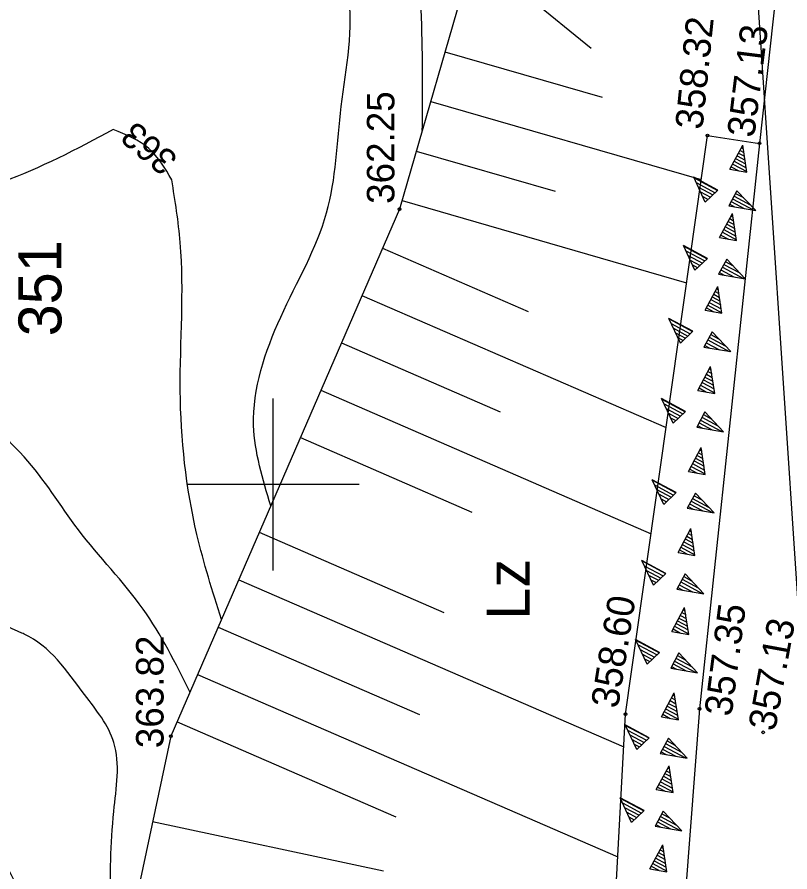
# Model space of a CAD drawing. Extents: x 4635329 to 4651863, y 5356628 to 5367582.
# Drawn here: x 4651179.57 to 4651202.03, y 5356645.09 to 5356669.94 of the extents above; entities that cross this region are included whole.
import ezdxf

# ---------------------------------------------------------------- set-up
doc = ezdxf.new("R2010")
doc.units = 0
for name, color, linetype in [('Level 12', 7, 'Continuous'), ('Level 4', 7, 'Continuous'), ('Level 44', 7, 'Continuous'), ('Level 45', 7, 'Continuous'), ('Level 46', 7, 'Continuous'), ('Level 47', 7, 'Continuous'), ('Level 48', 7, 'Continuous'), ('Level 49', 7, 'Continuous'), ('Level 5', 7, 'Continuous'), ('Level 50', 7, 'Continuous'), ('Level 60', 7, 'Continuous')]:
    doc.layers.add(name, color=color, linetype=linetype)

msp = doc.modelspace()

# ---------------------------------------------------------------- linework, layer by layer
at = {"layer": 'Level 4'}
msp.add_line((4651203.591, 5356632.939), (4651200.98, 5356672.325), dxfattribs=at)
at = {"layer": 'Level 44'}
for centre in [(4651199.635, 5356666.497), (4651201.145, 5356666.267), (4651190.685, 5356664.357), (4651197.255, 5356649.677), (4651199.405, 5356649.827), (4651201.255, 5356649.147), (4651184.035, 5356649.037)]:
    msp.add_circle(centre, 0.04, dxfattribs=at)
at = {"layer": 'Level 46'}
msp.add_line((4651179.706, 5356652.031), (4651177.706, 5356652.91), dxfattribs=at)
for points in [[(4651186.942, 5356655.734), (4651186.443, 5356658.066), (4651187.231, 5356661.219), (4651188.565, 5356664.25), (4651188.99, 5356667.342), (4651189.172, 5356670.677), (4651183.41, 5356675.407), (4651180.62, 5356675.589), (4651178.861, 5356675.735)], [(4651191.346, 5356666.645), (4651191.346, 5356669.024), (4651191.164, 5356672.662), (4651191.037, 5356674.114)], [(4651182.363, 5356666.668), (4651175.94, 5356664.78), (4651173.696, 5356665.325), (4651173.402, 5356665.355)], [(4651184.062, 5356665.204), (4651183.4, 5356666.114), (4651182.363, 5356666.668)], [(4651185.507, 5356652.429), (4651184.795, 5356654.897), (4651184.31, 5356659.08), (4651184.31, 5356663.385), (4651184.062, 5356665.204)], [(4651184.591, 5356650.319), (4651183.228, 5356652.73), (4651181.348, 5356655.034), (4651179.771, 5356657.156), (4651174.07, 5356659.581), (4651171.401, 5356659.824), (4651170.74, 5356660.291)], [(4651182.533, 5356641.982), (4651182.318, 5356644.059), (4651182.379, 5356646.848), (4651182.379, 5356648.849), (4651181.53, 5356650.244), (4651179.771, 5356652.002), (4651179.706, 5356652.031)], [(4651181.627, 5356637.725), (4651181.408, 5356639.209), (4651180.499, 5356642.422), (4651178.74, 5356646.121), (4651173.827, 5356650.062), (4651172.468, 5356650.413)]]:
    msp.add_spline(points, degree=3, dxfattribs=at)
at = {"layer": 'Level 48'}
for p, q in [((4651192.905, 5356671.773), (4651196.255, 5356669.031)), ((4651192.005, 5356668.926), (4651196.576, 5356667.606)), ((4651191.589, 5356667.485), (4651199.453, 5356665.213)), ((4651191.172, 5356666.044), (4651195.207, 5356664.879)), ((4651190.756, 5356664.603), (4651199.029, 5356662.213)), ((4651190.19, 5356663.216), (4651194.42, 5356661.38)), ((4651189.592, 5356661.84), (4651198.433, 5356658.003)), ((4651188.995, 5356660.464), (4651193.605, 5356658.463)), ((4651188.398, 5356659.088), (4651197.997, 5356654.921)), ((4651187.801, 5356657.712), (4651192.79, 5356655.547)), ((4651186.606, 5356654.96), (4651191.974, 5356652.63)), ((4651186.009, 5356653.584), (4651197.203, 5356648.725)), ((4651185.412, 5356652.208), (4651191.264, 5356649.668)), ((4651184.814, 5356650.832), (4651197.029, 5356645.53)), ((4651184.217, 5356649.456), (4651190.579, 5356646.695)), ((4651183.506, 5356646.55), (4651190.217, 5356645.121))]:
    msp.add_line(p, q, dxfattribs=at)
for points in [[(4651197.655, 5356677.577), (4651192.785, 5356671.627), (4651190.685, 5356664.357), (4651184.035, 5356649.037), (4651181.425, 5356636.777)], [(4651196.425, 5356634.457), (4651197.255, 5356649.677), (4651199.635, 5356666.497), (4651201.145, 5356666.267)]]:
    msp.add_lwpolyline(points, dxfattribs=at)
at = {"layer": 'Level 49'}
for p, q in [((4651200.289, 5356665.514), (4651200.663, 5356666.21)), ((4651200.583, 5356666.062), (4651200.694, 5356666.003)), ((4651200.626, 5356666.142), (4651200.677, 5356666.114)), ((4651200.782, 5356665.428), (4651200.663, 5356666.21)), ((4651200.455, 5356665.824), (4651200.744, 5356665.669)), ((4651200.498, 5356665.904), (4651200.728, 5356665.78)), ((4651200.541, 5356665.983), (4651200.712, 5356665.891)), ((4651200.328, 5356665.587), (4651200.547, 5356665.469)), ((4651200.37, 5356665.666), (4651200.779, 5356665.446)), ((4651200.413, 5356665.745), (4651200.762, 5356665.558)), ((4651200.289, 5356665.514), (4651200.782, 5356665.428)), ((4651199.935, 5356664.905), (4651199.239, 5356665.279)), ((4651199.571, 5356664.561), (4651199.239, 5356665.279)), ((4651199.245, 5356665.264), (4651199.928, 5356664.898)), ((4651199.308, 5356665.128), (4651199.859, 5356664.833)), ((4651199.372, 5356664.992), (4651199.79, 5356664.767)), ((4651199.435, 5356664.856), (4651199.721, 5356664.702)), ((4651199.935, 5356664.905), (4651199.571, 5356664.561)), ((4651200.494, 5356664.889), (4651200.258, 5356664.448)), ((4651200.454, 5356664.813), (4651200.681, 5356664.691)), ((4651201.037, 5356664.314), (4651200.494, 5356664.889)), ((4651199.498, 5356664.72), (4651199.652, 5356664.637)), ((4651199.561, 5356664.584), (4651199.583, 5356664.572)), ((4651200.326, 5356664.575), (4651200.706, 5356664.371)), ((4651200.368, 5356664.654), (4651200.987, 5356664.322)), ((4651200.411, 5356664.734), (4651200.876, 5356664.484)), ((4651200.258, 5356664.448), (4651201.037, 5356664.314)), ((4651200.283, 5356664.496), (4651200.426, 5356664.419)), ((4651199.988, 5356663.53), (4651200.362, 5356664.226)), ((4651200.283, 5356664.078), (4651200.394, 5356664.018)), ((4651200.325, 5356664.157), (4651200.376, 5356664.13)), ((4651200.481, 5356663.443), (4651200.362, 5356664.226)), ((4651200.155, 5356663.84), (4651200.444, 5356663.685)), ((4651200.197, 5356663.919), (4651200.427, 5356663.796)), ((4651200.24, 5356663.999), (4651200.411, 5356663.907)), ((4651200.027, 5356663.602), (4651200.246, 5356663.484)), ((4651200.07, 5356663.681), (4651200.478, 5356663.462)), ((4651200.112, 5356663.761), (4651200.461, 5356663.573)), ((4651199.988, 5356663.53), (4651200.481, 5356663.443)), ((4651199.635, 5356662.921), (4651198.938, 5356663.295)), ((4651199.271, 5356662.577), (4651198.938, 5356663.295)), ((4651198.945, 5356663.28), (4651199.628, 5356662.913)), ((4651199.008, 5356663.144), (4651199.559, 5356662.848)), ((4651199.071, 5356663.008), (4651199.49, 5356662.783)), ((4651199.134, 5356662.872), (4651199.42, 5356662.718)), ((4651199.635, 5356662.921), (4651199.271, 5356662.577)), ((4651200.194, 5356662.904), (4651199.957, 5356662.464)), ((4651200.153, 5356662.828), (4651200.38, 5356662.706)), ((4651200.736, 5356662.329), (4651200.194, 5356662.904)), ((4651199.197, 5356662.736), (4651199.351, 5356662.653)), ((4651199.26, 5356662.6), (4651199.282, 5356662.588)), ((4651200.025, 5356662.591), (4651200.406, 5356662.386)), ((4651200.068, 5356662.67), (4651200.686, 5356662.338)), ((4651200.11, 5356662.749), (4651200.576, 5356662.499)), ((4651199.957, 5356662.464), (4651200.736, 5356662.329)), ((4651199.983, 5356662.511), (4651200.125, 5356662.435)), ((4651199.565, 5356661.413), (4651199.939, 5356662.109)), ((4651200.057, 5356661.326), (4651199.939, 5356662.109)), ((4651199.816, 5356661.881), (4651199.987, 5356661.79)), ((4651199.859, 5356661.961), (4651199.97, 5356661.901)), ((4651199.902, 5356662.04), (4651199.953, 5356662.013)), ((4651199.689, 5356661.644), (4651200.038, 5356661.456)), ((4651199.731, 5356661.723), (4651200.02, 5356661.568)), ((4651199.774, 5356661.802), (4651200.004, 5356661.679)), ((4651199.565, 5356661.413), (4651200.057, 5356661.326)), ((4651199.604, 5356661.485), (4651199.823, 5356661.367)), ((4651199.646, 5356661.564), (4651200.055, 5356661.345)), ((4651199.211, 5356660.803), (4651198.515, 5356661.178)), ((4651198.847, 5356660.46), (4651198.515, 5356661.178)), ((4651198.521, 5356661.163), (4651199.204, 5356660.796)), ((4651198.584, 5356661.027), (4651199.135, 5356660.731)), ((4651198.647, 5356660.891), (4651199.066, 5356660.666)), ((4651198.711, 5356660.755), (4651198.997, 5356660.601)), ((4651198.774, 5356660.619), (4651198.928, 5356660.536)), ((4651199.211, 5356660.803), (4651198.847, 5356660.46)), ((4651199.77, 5356660.787), (4651199.534, 5356660.347)), ((4651199.687, 5356660.632), (4651200.152, 5356660.382)), ((4651199.729, 5356660.711), (4651199.957, 5356660.589)), ((4651200.313, 5356660.212), (4651199.77, 5356660.787)), ((4651198.837, 5356660.482), (4651198.859, 5356660.471)), ((4651199.534, 5356660.347), (4651200.313, 5356660.212)), ((4651199.559, 5356660.394), (4651199.702, 5356660.318)), ((4651199.602, 5356660.473), (4651199.982, 5356660.269)), ((4651199.644, 5356660.553), (4651200.263, 5356660.221)), ((4651199.353, 5356659.084), (4651199.727, 5356659.78)), ((4651199.647, 5356659.632), (4651199.758, 5356659.572)), ((4651199.69, 5356659.711), (4651199.741, 5356659.684)), ((4651199.846, 5356658.997), (4651199.727, 5356659.78)), ((4651199.52, 5356659.394), (4651199.808, 5356659.239)), ((4651199.562, 5356659.473), (4651199.792, 5356659.35)), ((4651199.605, 5356659.553), (4651199.776, 5356659.461)), ((4651199.392, 5356659.156), (4651199.611, 5356659.038)), ((4651199.434, 5356659.235), (4651199.843, 5356659.016)), ((4651199.477, 5356659.315), (4651199.826, 5356659.127)), ((4651199, 5356658.475), (4651198.303, 5356658.849)), ((4651198.636, 5356658.131), (4651198.303, 5356658.849)), ((4651199.353, 5356659.084), (4651199.846, 5356658.997)), ((4651198.309, 5356658.834), (4651198.992, 5356658.467)), ((4651198.373, 5356658.698), (4651198.923, 5356658.402)), ((4651198.436, 5356658.562), (4651198.854, 5356658.337)), ((4651198.499, 5356658.426), (4651198.785, 5356658.272)), ((4651199, 5356658.475), (4651198.636, 5356658.131)), ((4651199.558, 5356658.458), (4651199.322, 5356658.018)), ((4651199.518, 5356658.382), (4651199.745, 5356658.26)), ((4651200.101, 5356657.883), (4651199.558, 5356658.458)), ((4651198.562, 5356658.29), (4651198.716, 5356658.207)), ((4651198.625, 5356658.154), (4651198.647, 5356658.142)), ((4651199.39, 5356658.145), (4651199.77, 5356657.94)), ((4651199.432, 5356658.224), (4651200.051, 5356657.892)), ((4651199.475, 5356658.303), (4651199.94, 5356658.053)), ((4651199.322, 5356658.018), (4651200.101, 5356657.883)), ((4651199.347, 5356658.065), (4651199.49, 5356657.989)), ((4651199.081, 5356656.725), (4651199.455, 5356657.421)), ((4651199.573, 5356656.638), (4651199.455, 5356657.421)), ((4651199.29, 5356657.114), (4651199.52, 5356656.991)), ((4651199.332, 5356657.193), (4651199.503, 5356657.102)), ((4651199.375, 5356657.273), (4651199.486, 5356657.213)), ((4651199.418, 5356657.352), (4651199.469, 5356657.325)), ((4651199.162, 5356656.876), (4651199.571, 5356656.657)), ((4651199.205, 5356656.956), (4651199.554, 5356656.768)), ((4651199.247, 5356657.035), (4651199.536, 5356656.88)), ((4651199.081, 5356656.725), (4651199.573, 5356656.638)), ((4651199.119, 5356656.797), (4651199.339, 5356656.679)), ((4651198.727, 5356656.115), (4651198.03, 5356656.49)), ((4651198.363, 5356655.772), (4651198.03, 5356656.49)), ((4651198.037, 5356656.475), (4651198.72, 5356656.108)), ((4651198.1, 5356656.339), (4651198.651, 5356656.043)), ((4651198.163, 5356656.203), (4651198.582, 5356655.978)), ((4651198.727, 5356656.115), (4651198.363, 5356655.772)), ((4651198.227, 5356656.067), (4651198.513, 5356655.913)), ((4651198.29, 5356655.93), (4651198.444, 5356655.848)), ((4651199.286, 5356656.099), (4651199.049, 5356655.659)), ((4651199.16, 5356655.865), (4651199.779, 5356655.533)), ((4651199.203, 5356655.944), (4651199.668, 5356655.694)), ((4651199.245, 5356656.023), (4651199.473, 5356655.901)), ((4651199.828, 5356655.524), (4651199.286, 5356656.099)), ((4651198.353, 5356655.794), (4651198.375, 5356655.783)), ((4651199.049, 5356655.659), (4651199.828, 5356655.524)), ((4651199.075, 5356655.706), (4651199.218, 5356655.629)), ((4651199.118, 5356655.785), (4651199.498, 5356655.581)), ((4651198.78, 5356654.377), (4651199.154, 5356655.073)), ((4651199.074, 5356654.925), (4651199.185, 5356654.866)), ((4651199.117, 5356655.005), (4651199.168, 5356654.977)), ((4651199.273, 5356654.291), (4651199.154, 5356655.073)), ((4651198.946, 5356654.687), (4651199.235, 5356654.532)), ((4651198.989, 5356654.767), (4651199.219, 5356654.643)), ((4651199.032, 5356654.846), (4651199.203, 5356654.754)), ((4651198.78, 5356654.377), (4651199.273, 5356654.291)), ((4651198.819, 5356654.45), (4651199.038, 5356654.332)), ((4651198.861, 5356654.529), (4651199.27, 5356654.309)), ((4651198.904, 5356654.608), (4651199.253, 5356654.421)), ((4651198.426, 5356653.768), (4651197.73, 5356654.142)), ((4651198.063, 5356653.424), (4651197.73, 5356654.142)), ((4651197.736, 5356654.127), (4651198.419, 5356653.761)), ((4651197.799, 5356653.991), (4651198.35, 5356653.696)), ((4651197.863, 5356653.855), (4651198.281, 5356653.63)), ((4651197.926, 5356653.719), (4651198.212, 5356653.565)), ((4651198.426, 5356653.768), (4651198.063, 5356653.424)), ((4651198.985, 5356653.752), (4651198.749, 5356653.311)), ((4651198.945, 5356653.676), (4651199.172, 5356653.554)), ((4651199.528, 5356653.177), (4651198.985, 5356653.752)), ((4651197.989, 5356653.583), (4651198.143, 5356653.5)), ((4651198.052, 5356653.447), (4651198.074, 5356653.435)), ((4651198.817, 5356653.438), (4651199.197, 5356653.234)), ((4651198.859, 5356653.517), (4651199.478, 5356653.185)), ((4651198.902, 5356653.597), (4651199.367, 5356653.347)), ((4651198.749, 5356653.311), (4651199.528, 5356653.177)), ((4651198.774, 5356653.359), (4651198.917, 5356653.282)), ((4651198.598, 5356652.079), (4651198.972, 5356652.775)), ((4651198.935, 5356652.706), (4651198.986, 5356652.679)), ((4651199.091, 5356651.992), (4651198.972, 5356652.775)), ((4651198.765, 5356652.389), (4651199.054, 5356652.234)), ((4651198.807, 5356652.468), (4651199.037, 5356652.345)), ((4651198.85, 5356652.547), (4651199.021, 5356652.456)), ((4651198.893, 5356652.627), (4651199.004, 5356652.567)), ((4651198.637, 5356652.151), (4651198.856, 5356652.033)), ((4651198.68, 5356652.23), (4651199.088, 5356652.011)), ((4651198.722, 5356652.31), (4651199.071, 5356652.122)), ((4651198.598, 5356652.079), (4651199.091, 5356651.992)), ((4651198.245, 5356651.469), (4651197.548, 5356651.844)), ((4651197.881, 5356651.126), (4651197.548, 5356651.844)), ((4651197.555, 5356651.829), (4651198.238, 5356651.462)), ((4651197.618, 5356651.693), (4651198.169, 5356651.397)), ((4651197.681, 5356651.557), (4651198.1, 5356651.332)), ((4651197.744, 5356651.421), (4651198.031, 5356651.267)), ((4651198.245, 5356651.469), (4651197.881, 5356651.126)), ((4651198.804, 5356651.453), (4651198.567, 5356651.013)), ((4651199.346, 5356650.878), (4651198.804, 5356651.453)), ((4651197.807, 5356651.284), (4651197.961, 5356651.202)), ((4651197.87, 5356651.148), (4651197.892, 5356651.137)), ((4651198.678, 5356651.219), (4651199.296, 5356650.887)), ((4651198.72, 5356651.298), (4651199.186, 5356651.048)), ((4651198.763, 5356651.377), (4651198.99, 5356651.255)), ((4651198.567, 5356651.013), (4651199.346, 5356650.878)), ((4651198.593, 5356651.06), (4651198.735, 5356650.983)), ((4651198.635, 5356651.139), (4651199.016, 5356650.935)), ((4651198.296, 5356649.599), (4651198.67, 5356650.295)), ((4651198.633, 5356650.226), (4651198.684, 5356650.198)), ((4651198.789, 5356649.512), (4651198.67, 5356650.295)), ((4651198.462, 5356649.909), (4651198.751, 5356649.754)), ((4651198.505, 5356649.988), (4651198.735, 5356649.864)), ((4651198.548, 5356650.067), (4651198.718, 5356649.975)), ((4651198.59, 5356650.147), (4651198.701, 5356650.087)), ((4651198.335, 5356649.671), (4651198.554, 5356649.553)), ((4651198.377, 5356649.75), (4651198.786, 5356649.531)), ((4651198.42, 5356649.829), (4651198.769, 5356649.642)), ((4651198.296, 5356649.599), (4651198.789, 5356649.512)), ((4651197.942, 5356648.989), (4651197.246, 5356649.364)), ((4651197.578, 5356648.646), (4651197.246, 5356649.364)), ((4651197.252, 5356649.349), (4651197.935, 5356648.982)), ((4651197.315, 5356649.213), (4651197.866, 5356648.917)), ((4651197.379, 5356649.077), (4651197.797, 5356648.852)), ((4651197.442, 5356648.94), (4651197.728, 5356648.787)), ((4651197.942, 5356648.989), (4651197.578, 5356648.646)), ((4651198.501, 5356648.973), (4651198.265, 5356648.532)), ((4651199.044, 5356648.398), (4651198.501, 5356648.973)), ((4651197.505, 5356648.804), (4651197.659, 5356648.722)), ((4651197.568, 5356648.668), (4651197.59, 5356648.656)), ((4651198.333, 5356648.659), (4651198.713, 5356648.455)), ((4651198.375, 5356648.739), (4651198.994, 5356648.406)), ((4651198.418, 5356648.818), (4651198.883, 5356648.568)), ((4651198.46, 5356648.897), (4651198.688, 5356648.775)), ((4651198.265, 5356648.532), (4651199.044, 5356648.398)), ((4651198.29, 5356648.58), (4651198.433, 5356648.503)), ((4651198.145, 5356647.481), (4651198.518, 5356648.177)), ((4651198.637, 5356647.395), (4651198.518, 5356648.177)), ((4651198.396, 5356647.95), (4651198.567, 5356647.858)), ((4651198.439, 5356648.029), (4651198.55, 5356647.97)), ((4651198.481, 5356648.109), (4651198.533, 5356648.081)), ((4651198.268, 5356647.712), (4651198.617, 5356647.525)), ((4651198.311, 5356647.792), (4651198.6, 5356647.636)), ((4651198.354, 5356647.871), (4651198.584, 5356647.747)), ((4651198.145, 5356647.481), (4651198.637, 5356647.395)), ((4651198.183, 5356647.554), (4651198.403, 5356647.436)), ((4651198.226, 5356647.633), (4651198.635, 5356647.413)), ((4651197.791, 5356646.872), (4651197.094, 5356647.246)), ((4651197.427, 5356646.528), (4651197.094, 5356647.246)), ((4651197.101, 5356647.232), (4651197.784, 5356646.865)), ((4651197.164, 5356647.095), (4651197.715, 5356646.8)), ((4651197.227, 5356646.959), (4651197.646, 5356646.735)), ((4651197.29, 5356646.823), (4651197.577, 5356646.669)), ((4651197.354, 5356646.687), (4651197.508, 5356646.604)), ((4651197.791, 5356646.872), (4651197.427, 5356646.528)), ((4651198.35, 5356646.856), (4651198.113, 5356646.415)), ((4651198.267, 5356646.701), (4651198.732, 5356646.451)), ((4651198.309, 5356646.78), (4651198.536, 5356646.658)), ((4651198.892, 5356646.281), (4651198.35, 5356646.856)), ((4651197.417, 5356646.551), (4651197.439, 5356646.539)), ((4651198.139, 5356646.463), (4651198.282, 5356646.386)), ((4651198.181, 5356646.542), (4651198.562, 5356646.338)), ((4651198.224, 5356646.621), (4651198.842, 5356646.289)), ((4651198.113, 5356646.415), (4651198.892, 5356646.281)), ((4651197.963, 5356645.183), (4651198.337, 5356645.879)), ((4651198.257, 5356645.731), (4651198.368, 5356645.671)), ((4651198.3, 5356645.81), (4651198.351, 5356645.783)), ((4651198.456, 5356645.096), (4651198.337, 5356645.879)), ((4651198.13, 5356645.493), (4651198.419, 5356645.338)), ((4651198.172, 5356645.572), (4651198.402, 5356645.449)), ((4651198.215, 5356645.651), (4651198.386, 5356645.56)), ((4651197.963, 5356645.183), (4651198.456, 5356645.096)), ((4651198.002, 5356645.255), (4651198.221, 5356645.137)), ((4651198.044, 5356645.334), (4651198.453, 5356645.115)), ((4651198.087, 5356645.414), (4651198.436, 5356645.226))]:
    msp.add_line(p, q, dxfattribs=at)
at = {"layer": 'Level 50'}
for p, q in [((4651202.025, 5356674.277), (4651201.145, 5356666.267)), ((4651201.145, 5356666.267), (4651199.405, 5356649.827)), ((4651199.405, 5356649.827), (4651198.275, 5356635.267))]:
    msp.add_line(p, q, dxfattribs=at)
at = {"layer": 'Level 60'}
for p, q in [((4651187.015, 5356653.847), (4651187.015, 5356658.847)), ((4651189.515, 5356656.347), (4651184.515, 5356656.347))]:
    msp.add_line(p, q, dxfattribs=at)

# ---------------------------------------------------------------- texts
at = {"layer": 'Level 12'}
msp.add_text('Lz', height=1.25, rotation=90, dxfattribs=at).set_placement((4651194.465, 5356652.423))
at = {"layer": 'Level 45'}
for s, rotation, p in [('358.32', 84.1642, (4651199.488, 5356666.645)), ('357.13', 82.8899, (4651200.995, 5356666.415)), ('362.25', 90, (4651190.535, 5356664.507)), ('358.60', 80.8917, (4651197.033, 5356649.818)), ('357.35', 82.5922, (4651200.334, 5356649.587)), ('357.13', 79.681, (4651201.601, 5356649.156)), ('363.82', 90, (4651183.824, 5356648.686))]:
    msp.add_text(s, height=0.8, rotation=rotation, dxfattribs=at).set_placement(p)
at = {"layer": 'Level 47'}
msp.add_text('363', height=0.75, rotation=139.8076, dxfattribs=at).set_placement((4651184.279, 5356665.862))
at = {"layer": 'Level 5'}
msp.add_text('351', height=1.25, rotation=90, dxfattribs=at).set_placement((4651180.856, 5356660.658))

doc.saveas('drawing.dxf')
